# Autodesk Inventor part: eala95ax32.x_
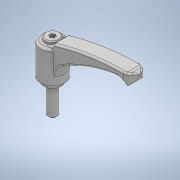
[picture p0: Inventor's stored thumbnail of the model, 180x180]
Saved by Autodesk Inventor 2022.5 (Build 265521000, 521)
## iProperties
Created: 2018-05
Part Number: eala95ax32.x_
Material: 一般
Document SubType Name: Modeling
Designer: imaocorp
Density: 1 g/cm^3
Appearance: 既定
Sending System: SOLIDWORKS 2016-2016286
MC: AMD64
MC_MODEL: AMD64 Family 21 Model 2 Stepping 0, AuthenticAMD
OS: Windows_NT
FRU: Parasolid Version 28.0, build 224,  7-29-2016
FORMAT: text
GUISE: transmit
KEY: eala95ax32
FILE: eala95ax32.x_t
DATE: Fri May 18 11:33:03 2018
Author: imaocorp
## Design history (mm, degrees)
feature "Base1"
node "ソリッド1"
